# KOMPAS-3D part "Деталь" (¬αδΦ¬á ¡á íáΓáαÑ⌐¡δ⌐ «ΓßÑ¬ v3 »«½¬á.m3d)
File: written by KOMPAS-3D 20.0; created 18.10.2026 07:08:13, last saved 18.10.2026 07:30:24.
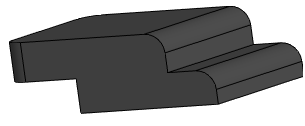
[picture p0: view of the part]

Document properties: Полное имя файла: D:\myProjects\Progect_esp32\box_compas\корпус\крышка на батарейный отсек v3 полка.m3d

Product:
- Part/product: Деталь
    Масса: 0.00105928

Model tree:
1. Эскиз:1
2. Элемент выдавливания:2
     Расстояние 1 = 7
3. Скругление:1  (with: Элемент выдавливания:2)
     Радиус = 0.8
4. Эскиз:2  (with: Элемент выдавливания:2)
5. Элемент выдавливания:3
     Расстояние 1 = 2
6. Скругление:2  (with: Элемент выдавливания:3, Элемент выдавливания:2)
     Радиус = 0.8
